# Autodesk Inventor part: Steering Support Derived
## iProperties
Length Units: 11269
Angle Units: 11279
Time Units: 11290
Mass Units: 11283
Shininess: 3
Angle Display Precision: 2
Document Length Units: 11269
Document Angle Units: 11279
Document Time Units: 11290
Document Mass Units: 11283
Document Length Units Precision: 3
Document Angle Units Precision: 2
Compacted: True
Created: 2001-08
Part Number: Steering Support Derived
Document SubType Name: Modeling
Designer: Martin Budgell
Density: 0.0
Volumn: 0.0
Area: 0.0
PropertySet Name: Model Information
Control State: 0
Master: False
Checked Out: False
Author: Martin Budgell
